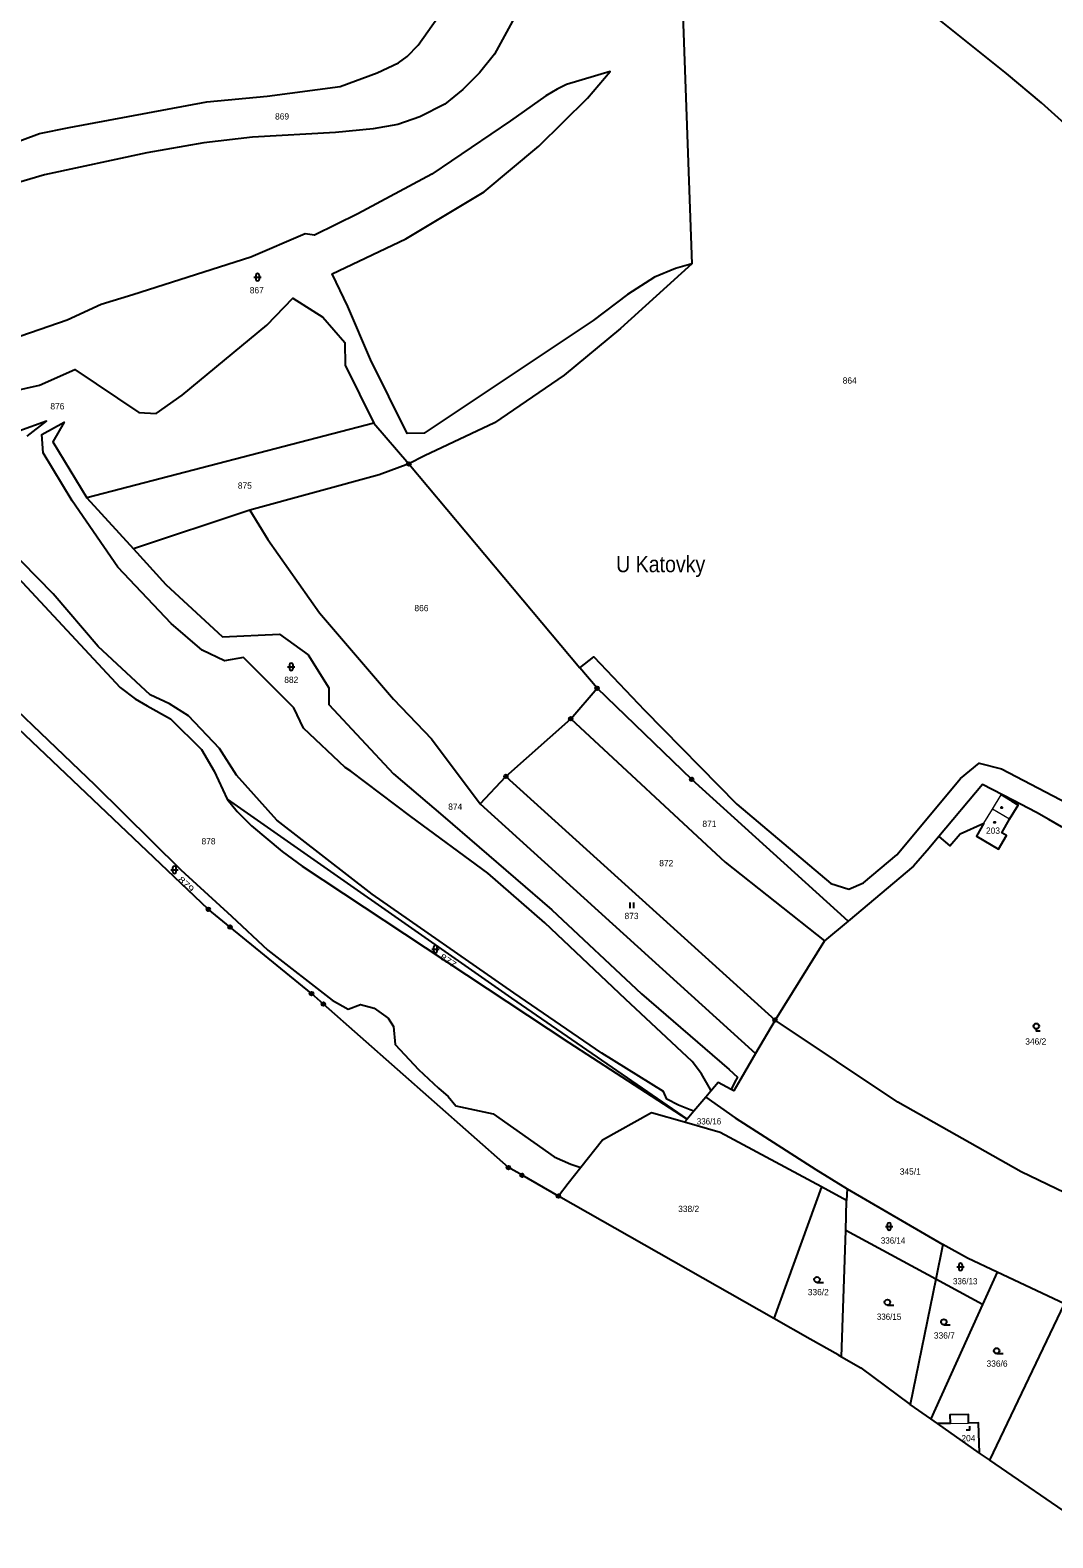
# Model space of a CAD drawing. Extents: x -754445 to -751443, y -1030748 to -1028224.
# Drawn here: x -754280.2 to -754003.3, y -1028971.2 to -1028563 of the extents above; entities that cross this region are included whole.
import ezdxf
from ezdxf.enums import TextEntityAlignment as Align

# ---------------------------------------------------------------- set-up
doc = ezdxf.new("R2010")
doc.units = 0
doc.header["$LTSCALE"] = 0.68
for name, color, linetype, lineweight in [('1', 7, 'Continuous', 25), ('3', 7, 'Continuous', 25), ('4', 7, 'Continuous', 13), ('5', 7, 'Continuous', 25), ('7', 7, 'Continuous', 13), ('8', 7, 'Continuous', 25)]:
    doc.layers.add(name, color=color, linetype=linetype, lineweight=lineweight)
doc.layers.add('2', color=7, linetype='Continuous')

msp = doc.modelspace()

# ---------------------------------------------------------------- linework, layer by layer
at = {"layer": '1'}
for p, q in [((-754187.11, -1028669.45), (-754177.67, -1028680.46)), ((-754177.67, -1028680.46), (-754131.34, -1028735.65)), ((-754220.68, -1028693.01), (-754252.24, -1028703.48)), ((-754231.95, -1028801.06), (-754283.35, -1028752.23)), ((-754151.39, -1028765.07), (-754078.54, -1028831.05)), ((-754158.4, -1028772.47), (-754083.82, -1028840.09)), ((-754226.04, -1028805.89), (-754231.95, -1028801.06)), ((-754204.02, -1028823.88), (-754226.04, -1028805.89)), ((-754200.8, -1028826.72), (-754204.02, -1028823.88)), ((-754150.7, -1028870.99), (-754200.8, -1028826.72)), ((-754097.29, -1028851.92), (-754100.5, -1028855.71)), ((-754147.03, -1028873.09), (-754150.7, -1028870.99)), ((-754059.04, -1028876.71), (-754059.15, -1028879.94)), ((-754035, -1028901.23), (-754059.41, -1028888.01)), ((-754035, -1028901.23), (-754041.96, -1028935.12)), ((-754022.34, -1028908.09), (-754035, -1028901.23)), ((-754061.46, -1028921.71), (-754069, -1028917.44)), ((-754061.46, -1028921.71), (-754060.53, -1028922.24)), ((-754036.39, -1028939.02), (-754041.96, -1028935.12))]:
    msp.add_line(p, q, dxfattribs=at)
for points in [[(-754068.82, -1028536.93), (-754076.64, -1028533.46), (-754104.72, -1028523.79), (-754101.08, -1028626.27)], [(-753985.37, -1028607.36), (-753989.46, -1028600.18), (-753996.44, -1028591.64), (-754006.4, -1028582.67), (-754015.86, -1028574.76), (-754050.65, -1028546.89), (-754057.94, -1028541.76), (-754068.82, -1028536.93)], [(-754304.59, -1028600.98), (-754277.62, -1028590.98), (-754269.62, -1028589.35), (-754232.39, -1028582.42), (-754216.02, -1028580.89), (-754196.26, -1028578.27), (-754186.28, -1028574.61), (-754180.49, -1028571.9), (-754178.16, -1028570.16), (-754175.15, -1028567.09), (-754169.88, -1028559.69)], [(-754147.98, -1028557.58), (-754154.47, -1028569.48), (-754158.52, -1028574.57), (-754163.07, -1028579.12), (-754167.92, -1028583.03), (-754174.69, -1028586.44), (-754180.66, -1028588.58), (-754187.34, -1028589.69), (-754197.51, -1028590.69), (-754219.95, -1028592), (-754233.19, -1028593.49), (-754248.62, -1028596.24), (-754276.26, -1028602.21), (-754301.14, -1028609.5)], [(-754101.08, -1028626.27), (-754105.46, -1028627.57), (-754111.12, -1028629.91), (-754118.46, -1028634.57), (-754127.77, -1028641.64), (-754173.49, -1028672.1), (-754178.09, -1028672.24), (-754188.01, -1028652.19), (-754194.16, -1028637.8), (-754198.46, -1028628.97), (-754178.5, -1028619.56), (-754157.26, -1028606.78), (-754142.5, -1028594.39), (-754129.28, -1028581.41), (-754123.15, -1028574.18), (-754134.98, -1028577.7), (-754137.54, -1028579.03), (-754140.54, -1028580.82), (-754150.11, -1028587.56), (-754171.41, -1028601.98), (-754191.51, -1028612.74), (-754203.21, -1028618.52), (-754205.76, -1028618.12), (-754220.48, -1028624.51), (-754252.42, -1028634.66), (-754260.96, -1028637.34), (-754270.12, -1028641.52), (-754287.67, -1028647.61)], [(-754101.08, -1028626.27), (-754120.35, -1028643.79), (-754135.64, -1028656.39), (-754154.46, -1028669.38), (-754173.41, -1028678.32), (-754177.67, -1028680.46)], [(-754288.58, -1028661.59), (-754277.64, -1028659.11), (-754268.05, -1028654.91), (-754250.73, -1028666.52), (-754246.1, -1028666.85), (-754239.06, -1028661.88), (-754216.13, -1028642.92), (-754209.05, -1028635.61), (-754200.91, -1028640.69), (-754194.99, -1028647.57), (-754194.86, -1028653.76), (-754187.11, -1028669.45)], [(-754324.12, -1028670.25), (-754305.07, -1028688.4), (-754284.66, -1028709.94), (-754255.8, -1028740.96), (-754251.74, -1028744.08), (-754248.54, -1028746.01), (-754242.17, -1028749.48), (-754233.82, -1028757.78), (-754230.36, -1028763.63), (-754226.82, -1028771.21)], [(-754280.97, -1028672.91), (-754275.75, -1028668.89), (-754283.29, -1028671.56)], [(-754095.94, -1028850.33), (-754096.03, -1028849.84), (-754098.41, -1028845.64), (-754100.97, -1028842.25), (-754119.06, -1028825.43), (-754140.85, -1028804.7), (-754156.24, -1028791.3), (-754177.16, -1028775.97), (-754193.36, -1028763.7), (-754194.86, -1028762.67), (-754206.16, -1028751.98), (-754208.83, -1028746.51), (-754222.47, -1028732.89), (-754227.61, -1028733.77), (-754233.64, -1028730.87), (-754242.02, -1028723.68), (-754256.46, -1028708.4), (-754268.82, -1028690.5), (-754276.64, -1028677.47), (-754277.01, -1028672.53), (-754270.98, -1028669.14), (-754274.08, -1028674.46), (-754264.84, -1028689.69)], [(-754187.11, -1028669.45), (-754264.84, -1028689.69), (-754252.24, -1028703.48)], [(-754177.67, -1028680.46), (-754185.71, -1028683.4), (-754220.68, -1028693.01)], [(-754100.5, -1028855.71), (-754101.53, -1028855.37), (-754104.7, -1028854.08), (-754107.87, -1028852.44), (-754108.74, -1028850.39), (-754125.44, -1028840.03), (-754149.24, -1028823.64), (-754187.6, -1028796.97), (-754213.44, -1028776.89), (-754224.32, -1028764.78), (-754228.95, -1028757.52), (-754237.35, -1028748.65), (-754242.5, -1028745.41), (-754247.65, -1028742.97), (-754261.75, -1028729.9), (-754273.95, -1028715.68), (-754299.38, -1028689.71)], [(-754220.68, -1028693.01), (-754215.82, -1028700.89), (-754201.83, -1028720.81), (-754181.83, -1028744.12), (-754171.56, -1028754.87), (-754158.4, -1028772.47), (-754151.39, -1028765.07), (-754133.83, -1028749.47)], [(-754252.24, -1028703.48), (-754243.44, -1028713.1), (-754228.07, -1028727.27), (-754212.72, -1028726.59), (-754204.89, -1028732.13), (-754199.3, -1028741.12), (-754199.29, -1028745.62), (-754181.86, -1028764.4), (-754168.47, -1028775.75), (-754138.92, -1028801.24), (-754114.64, -1028823.93), (-754090.95, -1028844.47), (-754088.74, -1028846.53), (-754089.52, -1028847.97), (-754090.39, -1028849.88)], [(-754298.56, -1028733.1), (-754262.66, -1028767.36), (-754239.42, -1028790.34), (-754225.71, -1028802.93), (-754215.83, -1028812.15), (-754198.42, -1028825.68), (-754194.06, -1028828.13), (-754190.73, -1028826.82), (-754187.08, -1028827.84), (-754183.28, -1028830.57), (-754181.82, -1028832.8), (-754181.35, -1028837.66), (-754175.07, -1028844.4), (-754169.61, -1028849.48), (-754167.02, -1028851.78), (-754164.96, -1028854.23), (-754154.82, -1028856.45), (-754138.35, -1028868.05), (-754133.82, -1028870.06), (-754131.11, -1028870.97)], [(-754133.83, -1028749.47), (-754126.69, -1028741.19), (-754131.34, -1028735.65)], [(-754131.34, -1028735.65), (-754127.59, -1028732.72), (-754113.89, -1028747.12), (-754088.91, -1028772.63), (-754063.41, -1028794.09), (-754058.54, -1028795.58), (-754054.61, -1028793.87), (-754045.57, -1028786.3), (-754028.3, -1028765.67), (-754023.24, -1028761.52), (-754017.21, -1028763.02), (-753997.37, -1028773.4), (-753989.77, -1028775.87), (-753982.55, -1028776.26)], [(-754058.74, -1028804.24), (-754101.1, -1028765.9), (-754126.69, -1028741.19)], [(-754133.83, -1028749.47), (-754092.03, -1028788.27), (-754065.17, -1028809.64)], [(-754014.17, -1028771.55), (-754022.4, -1028767.27), (-754034.19, -1028781.39)], [(-754226.82, -1028771.21), (-754224.13, -1028774.59), (-754220.25, -1028778.48), (-754211.99, -1028785.44), (-754206.56, -1028789.42), (-754134.33, -1028837.13), (-754102.34, -1028857.88)], [(-754226.82, -1028771.21), (-754149.84, -1028825.08), (-754102.34, -1028857.88)], [(-754034.19, -1028781.39), (-754031.18, -1028783.91), (-754028.41, -1028780.6), (-754021.97, -1028777.78), (-754023.97, -1028781.29), (-754018.07, -1028784.76), (-754015.87, -1028781.07), (-754017.14, -1028780.39), (-754015.02, -1028776.67), (-754012.73, -1028772.83), (-754014.36, -1028771.86), (-754014.17, -1028771.55)], [(-753943.75, -1028858.84), (-753948.74, -1028849.75), (-753958.93, -1028828.1), (-753973.84, -1028790.48), (-753983.68, -1028786.76), (-754001.01, -1028778.72), (-754004.38, -1028776.77), (-754007.79, -1028774.87), (-754014.17, -1028771.55)], [(-754034.19, -1028781.39), (-754036.82, -1028784.55), (-754041.02, -1028789.35), (-754058.74, -1028804.24)], [(-754058.74, -1028804.24), (-754065.17, -1028809.64), (-754078.54, -1028831.05)], [(-753981.13, -1028886.96), (-754011.9, -1028872.13), (-754045.3, -1028853.3), (-754078.54, -1028831.05), (-754083.82, -1028840.09)], [(-754083.82, -1028840.09), (-754087.83, -1028846.97), (-754089.73, -1028850.23), (-754090.39, -1028849.88)], [(-754090.39, -1028849.88), (-754093.95, -1028848), (-754095.94, -1028850.33), (-754097.29, -1028851.92)], [(-754097.29, -1028851.92), (-754089.37, -1028857.56), (-754067.52, -1028871.52), (-754059.04, -1028876.71), (-754033.07, -1028891.81)], [(-754103.06, -1028858.72), (-754111.97, -1028856.14), (-754125.28, -1028863.56), (-754131.11, -1028870.97)], [(-754100.5, -1028855.71), (-754102.34, -1028857.88), (-754103.06, -1028858.72)], [(-754066, -1028876.25), (-754093.35, -1028861.53), (-754103.06, -1028858.72)], [(-754069, -1028917.44), (-754078.83, -1028911.85), (-754137.16, -1028878.73), (-754147.03, -1028873.09)], [(-754131.11, -1028870.97), (-754134.51, -1028875.3), (-754137.16, -1028878.73)], [(-754059.15, -1028879.94), (-754066, -1028876.25), (-754078.83, -1028911.85)], [(-754060.53, -1028922.24), (-754059.41, -1028888.01), (-754059.15, -1028879.94)], [(-754018.36, -1028899.33), (-754026.44, -1028895.5), (-754033.07, -1028891.81), (-754035, -1028901.23)], [(-754018.36, -1028899.33), (-754022.34, -1028908.09), (-754036.39, -1028939.02)], [(-754020.42, -1028950.19), (-754000.2, -1028907.92), (-754018.36, -1028899.33)], [(-754060.53, -1028922.24), (-754055.27, -1028925.23), (-754041.96, -1028935.12)], [(-754023.14, -1028948.28), (-754034.51, -1028940.33), (-754036.39, -1028939.02)], [(-754023.14, -1028948.28), (-754023.42, -1028940.12), (-754026.12, -1028940.17), (-754026.17, -1028937.84), (-754031.25, -1028937.95), (-754031.15, -1028940.27), (-754034.51, -1028940.33)], [(-754020.42, -1028950.19), (-754020.51, -1028950.13), (-754023.14, -1028948.28)], [(-753989.77, -1028971.25), (-753995.91, -1028967.03), (-754020.42, -1028950.19)]]:
    msp.add_lwpolyline(points, dxfattribs=at)
at = {"layer": '3'}
for p, q in [((-754219.111, -1028629.421), (-754219.111, -1028630.422)), ((-754218.109, -1028630.422), (-754218.109, -1028629.421)), ((-754219.611, -1028629.921), (-754217.609, -1028629.921)), ((-754210.491, -1028735.391), (-754208.489, -1028735.391)), ((-754209.991, -1028734.891), (-754209.991, -1028735.892)), ((-754208.989, -1028735.892), (-754208.989, -1028734.891)), ((-754242.141, -1028790.351), (-754240.139, -1028790.351)), ((-754241.641, -1028789.851), (-754241.641, -1028790.852)), ((-754240.639, -1028790.852), (-754240.639, -1028789.851)), ((-754117.751, -1028800.71), (-754117.751, -1028799.21)), ((-754116.75, -1028800.71), (-754116.75, -1028799.21)), ((-754171.481, -1028811.831), (-754169.479, -1028811.831)), ((-754170.981, -1028811.331), (-754170.981, -1028812.332)), ((-754169.979, -1028812.332), (-754169.979, -1028811.331)), ((-754048.171, -1028886.421), (-754048.171, -1028887.422)), ((-754047.169, -1028887.422), (-754047.169, -1028886.421)), ((-754048.671, -1028886.921), (-754046.669, -1028886.921)), ((-754029.301, -1028897.891), (-754027.299, -1028897.891)), ((-754028.801, -1028897.391), (-754028.801, -1028898.392)), ((-754027.799, -1028898.392), (-754027.799, -1028897.391)), ((-754067.183, -1028902.09), (-754065.433, -1028902.09)), ((-754048.123, -1028908.23), (-754046.373, -1028908.23)), ((-754032.843, -1028913.53), (-754031.093, -1028913.53)), ((-754018.533, -1028921.36), (-754016.783, -1028921.36))]:
    msp.add_line(p, q, dxfattribs=at)
for points in [[(-754007.8, -1028833.452), (-754007.8, -1028833.95), (-754006.799, -1028833.95)], [(-754026.791, -1028942.01), (-754025.79, -1028942.01), (-754025.79, -1028941.01)]]:
    msp.add_lwpolyline(points, dxfattribs=at)
for centre in [(-754007.7993, -1028832.7009), (-754067.1829, -1028901.3398), (-754048.1229, -1028907.4798), (-754032.8429, -1028912.7798), (-754018.5329, -1028920.6098)]:
    msp.add_circle(centre, 0.75, dxfattribs=at)
for centre, start, end in [((-754218.61, -1028629.4209), 0, 180), ((-754218.61, -1028630.4209), 180, 359.98789), ((-754209.49, -1028734.8909), 0, 180), ((-754209.49, -1028735.8909), 180, 359.98789), ((-754241.14, -1028789.8509), 0, 180), ((-754241.14, -1028790.8509), 180, 359.98789), ((-754170.48, -1028811.3309), 0, 180), ((-754170.48, -1028812.3309), 180, 359.98789), ((-754047.67, -1028886.4209), 0, 180), ((-754047.67, -1028887.4209), 180, 359.98789), ((-754028.3, -1028897.3909), 0, 180), ((-754028.3, -1028898.3909), 180, 359.98789)]:
    msp.add_arc(centre, 0.5, start, end, dxfattribs=at)
at = {"layer": '4'}
for p, q in [((-754019.62, -1028773.92), (-754017.32, -1028770.09)), ((-754017.32, -1028770.09), (-754014.36, -1028771.86)), ((-754021.97, -1028777.78), (-754019.62, -1028773.92)), ((-754015.02, -1028776.67), (-754019.62, -1028773.92)), ((-754031.15, -1028940.27), (-754026.12, -1028940.17))]:
    msp.add_line(p, q, dxfattribs=at)
at = {"layer": '5'}
for centre in [(-754017.1868, -1028773.5292), (-754019.0968, -1028777.5092)]:
    msp.add_circle(centre, 0.175, dxfattribs=at)
at = {"layer": '8'}
for centre, radius in [((-754177.67, -1028680.4599), 0.5), ((-754177.67, -1028680.4599), 0.0303), ((-754126.69, -1028741.1899), 0.5), ((-754126.69, -1028741.1899), 0.0303), ((-754133.83, -1028749.4699), 0.5), ((-754133.83, -1028749.4699), 0.0303), ((-754151.39, -1028765.0699), 0.5), ((-754151.39, -1028765.0699), 0.0303), ((-754101.1, -1028765.8999), 0.5), ((-754101.1, -1028765.8999), 0.0303), ((-754231.95, -1028801.0599), 0.5), ((-754231.95, -1028801.0599), 0.0303), ((-754226.04, -1028805.8899), 0.5), ((-754226.04, -1028805.8899), 0.0303), ((-754204.02, -1028823.8799), 0.5), ((-754204.02, -1028823.8799), 0.0303), ((-754200.8, -1028826.7199), 0.5), ((-754200.8, -1028826.7199), 0.0303), ((-754078.54, -1028831.0499), 0.5), ((-754078.54, -1028831.0499), 0.0303), ((-754150.7, -1028870.9899), 0.5), ((-754150.7, -1028870.9899), 0.0303), ((-754147.03, -1028873.0899), 0.5), ((-754147.03, -1028873.0899), 0.0303), ((-754137.16, -1028878.7299), 0.5), ((-754137.16, -1028878.7299), 0.0303)]:
    msp.add_circle(centre, radius, dxfattribs=at)

# ---------------------------------------------------------------- texts
at = {"layer": '2'}
for s, p in [('869', (-754211.989, -1028587.216)), ('867', (-754218.829, -1028634.286)), ('864', (-754058.319, -1028658.736)), ('876', (-754272.809, -1028665.706)), ('875', (-754222.059, -1028687.186)), ('866', (-754174.259, -1028720.346)), ('882', (-754209.489, -1028739.756)), ('874', (-754165.109, -1028774.116)), ('871', (-754096.299, -1028778.756)), ('203', (-754019.529, -1028780.61)), ('878', (-754231.889, -1028783.486)), ('872', (-754107.979, -1028789.396)), ('873', (-754117.379, -1028803.716)), ('346/2', (-754007.95, -1028837.69)), ('345/1', (-754041.92, -1028872.91)), ('338/2', (-754101.91, -1028883.02)), ('336/2', (-754066.83, -1028905.55)), ('336/7', (-754032.69, -1028917.29)), ('336/6', (-754018.43, -1028924.92)), ('204', (-754026.189, -1028945.12))]:
    msp.add_text(s, height=1.7, dxfattribs=at).set_placement(p, align=Align.CENTER)
for s, rotation, width, p in [('879', 316, 1.3, (-754238.5495, -1028794.8893)), ('877', 326, 1.25, (-754167.5053, -1028815.6578))]:
    msp.add_text(s, height=1.7, rotation=rotation, dxfattribs=dict(at, width=width)).set_placement(p, align=Align.CENTER)
at = {"layer": '2', "width": 0.95}
for s, p in [('336/16', (-754096.409, -1028859.32)), ('336/14', (-754046.579, -1028891.58)), ('336/13', (-754027.059, -1028902.61)), ('336/15', (-754047.669, -1028912.22))]:
    msp.add_text(s, height=1.7, dxfattribs=at).set_placement(p, align=Align.CENTER)
at = {"layer": '7', "width": 0.9}
msp.add_text('U Katovky', height=4.4, dxfattribs=at).set_placement((-754109.489, -1028709.79), align=Align.CENTER)

doc.saveas('drawing.dxf')
